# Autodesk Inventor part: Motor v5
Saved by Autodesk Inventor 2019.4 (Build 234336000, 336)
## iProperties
Created: 2020-06
Part Number: Motor v5
Material: Generic
Document SubType Name: Modeling
Designer: Administrator
Density: 1 g/cm^3
Appearance: Default
Title: Motor v5
Author: Administrator
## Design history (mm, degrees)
